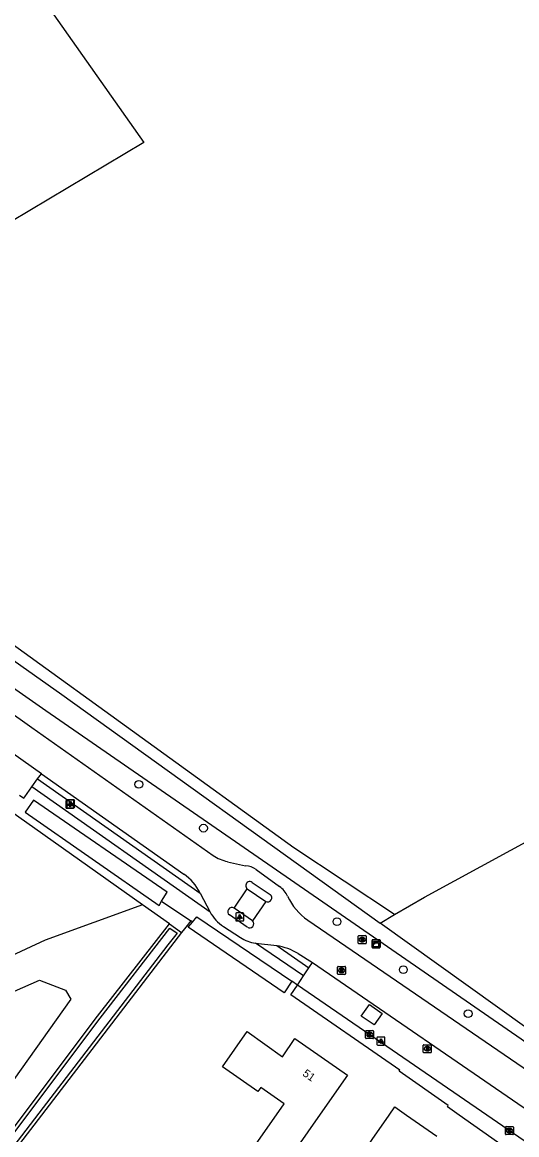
# Model space of a CAD drawing. Extents: x 163863 to 164644, y 379566 to 382155.
# Drawn here: x 164288.5 to 164350.3, y 381747.5 to 381886.6 of the extents above; entities that cross this region are included whole.
import ezdxf

# ---------------------------------------------------------------- set-up
doc = ezdxf.new("R2010")
doc.units = 0
for name, color, linetype in [('IMGEO_Boom', 7, 'Continuous'), ('IMGEO_Brandkraan', 7, 'Continuous'), ('IMGEO_Duiker', 7, 'Continuous'), ('IMGEO_Erf', 7, 'Continuous'), ('IMGEO_Fietspad_open', 7, 'Continuous'), ('IMGEO_Grasland_agrarisch', 7, 'Continuous'), ('IMGEO_Grasland_overig', 7, 'Continuous'), ('IMGEO_Groenvoorziening', 7, 'Continuous'), ('IMGEO_Kast', 7, 'Continuous'), ('IMGEO_Kolk', 7, 'Continuous'), ('IMGEO_Lichtpunt', 7, 'Continuous'), ('IMGEO_Loofbos', 7, 'Continuous'), ('IMGEO_Pand', 7, 'Continuous'), ('IMGEO_Pand_nummerreeks', 7, 'Continuous'), ('IMGEO_Parkeervlak_open', 7, 'Continuous'), ('IMGEO_Rijbaan_lokaal_gesloten', 7, 'Continuous'), ('IMGEO_Rijbaan_lokaal_open', 7, 'Continuous'), ('IMGEO_Rioolput', 7, 'Continuous'), ('IMGEO_Voetpad_onverhard', 7, 'Continuous'), ('IMGEO_Voetpad_open', 7, 'Continuous'), ('IMGEO_Waterloop', 7, 'Continuous')]:
    doc.layers.add(name, color=color, linetype=linetype)

msp = doc.modelspace()

# ---------------------------------------------------------------- linework, layer by layer
at = {"layer": 'IMGEO_Boom'}
for centre in [(164303.04, 381791.33), (164311.13, 381785.86), (164327.82, 381774.17), (164336.11, 381768.17), (164344.22, 381762.68)]:
    msp.add_circle(centre, 0.489, dxfattribs=at)
at = {"layer": 'IMGEO_Brandkraan'}
for p, q in [((164338.61, 381757.86), (164338.61, 381758.72)), ((164338.69, 381758.79), (164339.54, 381758.79)), ((164339.1, 381758.57), (164339.12, 381758.57)), ((164339.61, 381758.72), (164339.61, 381757.86)), ((164339.54, 381757.79), (164338.69, 381757.79)), ((164339.12, 381758.01), (164339.1, 381758.01))]:
    msp.add_line(p, q, dxfattribs=at)
for points in [[(164338.61, 381757.86), (164338.61, 381758.72)], [(164338.69, 381758.79), (164339.54, 381758.79)], [(164338.96, 381758.49), (164338.96, 381758.09), (164339.17, 381758.09)], [(164339.19, 381758.49), (164338.96, 381758.49)], [(164339.14, 381758.41), (164339.08, 381758.41), (164339.08, 381758.33)], [(164339.08, 381758.33), (164339.14, 381758.33)], [(164339.15, 381758.26), (164339.08, 381758.26), (164339.08, 381758.17)], [(164339.08, 381758.17), (164339.15, 381758.17)], [(164339.61, 381758.72), (164339.61, 381757.86)], [(164339.54, 381757.79), (164338.69, 381757.79)]]:
    msp.add_lwpolyline(points, dxfattribs=at)
for centre, radius, start, end in [((164338.69, 381758.71), 0.0765, 91.552, 178.448), ((164338.69, 381758.71), 0.0765, 91.552, 178.448), ((164339.14, 381758.37), 0.0379, 267.8285, 90.9355), ((164339.15, 381758.22), 0.0404, 269.8759, 90.5077), ((164339.18, 381758.34), 0.251, 268.6676, 293.5347), ((164339.19, 381758.34), 0.145, 59.4692, 91.5367), ((164339.22, 381758.39), 0.0922, 285.5137, 58.1501), ((164339.22, 381758.2), 0.105, 301.3115, 78.989), ((164339.54, 381758.71), 0.0765, 1.552, 88.448), ((164339.54, 381758.71), 0.0765, 1.552, 88.448), ((164338.69, 381757.86), 0.0765, 181.552, 268.448), ((164338.69, 381757.86), 0.0765, 181.552, 268.448), ((164339.54, 381757.86), 0.0765, 271.552, 358.448), ((164339.54, 381757.86), 0.0765, 271.552, 358.448)]:
    msp.add_arc(centre, radius, start, end, dxfattribs=at)
for centre, major_axis, ratio, start_param, end_param in [((164339.1, 381758.29), (-0.387, 0.002), 0.722429, 4.712389, 7.853982), ((164339.12, 381758.29), (-0.39, 0.002), 0.717154, 1.570796, 4.712389)]:
    msp.add_ellipse(centre, major_axis=major_axis, ratio=ratio, start_param=start_param, end_param=end_param, dxfattribs=at)
at = {"layer": 'IMGEO_Duiker'}
msp.add_lwpolyline([(164305.89, 381776.73), (164309.53, 381774.29)], dxfattribs=at)
at = {"layer": 'IMGEO_Erf'}
msp.add_lwpolyline([(164308.4, 381772.83), (164307.02, 381771.02), (164290.86, 381750), (164280.77, 381736.89), (164280.48, 381736.47), (164297.43, 381715.02)], dxfattribs=at)
at = {"layer": 'IMGEO_Fietspad_open'}
for points in [[(164289.68, 381791.02), (164290.39, 381792.01)], [(164290.39, 381792.01), (164310.71, 381777.75)], [(164311.95, 381775.37), (164289.68, 381791.02)], [(164323.62, 381767.41), (164317.65, 381771.48)], [(164320.29, 381771.18), (164324.32, 381768.39)], [(164323.62, 381767.41), (164324.32, 381768.39)]]:
    msp.add_lwpolyline(points, dxfattribs=at)
at = {"layer": 'IMGEO_Grasland_agrarisch'}
for points in [[(164278.81, 381906.76), (164279.85, 381905.36), (164303.69, 381871.55), (164284.62, 381860.24), (164259.76, 381889.45), (164267.39, 381895.77), (164258.03, 381908.47), (164254.79, 381905.94), (164252.4, 381909.27)], [(164335.01, 381775.05), (164338.75, 381777.23), (164392.73, 381806.6), (164404.25, 381812.22)]]:
    msp.add_lwpolyline(points, dxfattribs=at)
at = {"layer": 'IMGEO_Grasland_overig'}
for points in [[(164335.01, 381775.05), (164322.43, 381783.41), (164286.01, 381809.75), (164256.46, 381829.63), (164222.91, 381852.77), (164211.76, 381860.7), (164201.66, 381868.74), (164208.65, 381876.06), (164252.4, 381909.27)], [(164333.2, 381774), (164335.01, 381775.05)]]:
    msp.add_lwpolyline(points, dxfattribs=at)
at = {"layer": 'IMGEO_Groenvoorziening'}
for points in [[(164306.86, 381773.91), (164308.4, 381772.83)], [(164309.77, 381774.13), (164309.53, 381774.29), (164308.75, 381773.28), (164308.4, 381772.83)], [(164322.9, 381766.25), (164322.17, 381766.72)]]:
    msp.add_lwpolyline(points, dxfattribs=at)
at = {"layer": 'IMGEO_Kast'}
for p, q in [((164332.21, 381770.99), (164332.21, 381771.83)), ((164332.21, 381771.83), (164332.21, 381770.99)), ((164332.28, 381771.91), (164333.12, 381771.91)), ((164333.12, 381771.91), (164332.28, 381771.91)), ((164333.13, 381770.92), (164332.29, 381770.92)), ((164332.29, 381770.92), (164333.13, 381770.92)), ((164333.21, 381771.84), (164333.21, 381771)), ((164333.21, 381771), (164333.21, 381771.84))]:
    msp.add_line(p, q, dxfattribs=at)
for points in [[(164332.4, 381771.71), (164333, 381771.71), (164333, 381771.62), (164332.4, 381771.62), (164332.4, 381771.71)], [(164332.4, 381771.53), (164333, 381771.53), (164333, 381771.04), (164332.4, 381771.04), (164332.4, 381771.53)]]:
    msp.add_lwpolyline(points, dxfattribs=at)
msp.add_circle((164332.49, 381771.38), 0.0377, dxfattribs=at)
for centre, start, end in [((164332.29, 381771.84), 92.4484, 184.2845), ((164332.29, 381771.84), 92.4484, 184.2845), ((164332.29, 381770.99), 182.4484, 274.2845), ((164332.29, 381770.99), 182.4484, 274.2845), ((164333.13, 381771.84), 2.4484, 94.2845), ((164333.13, 381771.84), 2.4484, 94.2845), ((164333.13, 381770.99), 272.4484, 4.2845), ((164333.13, 381770.99), 272.4484, 4.2845)]:
    msp.add_arc(centre, 0.0779, start, end, dxfattribs=at)
at = {"layer": 'IMGEO_Kolk'}
for p, q in [((164331.4, 381759.64), (164331.4, 381760.49)), ((164331.47, 381760.57), (164332.32, 381760.57)), ((164332.32, 381759.57), (164331.47, 381759.57)), ((164331.91, 381759.79), (164331.88, 381759.79)), ((164331.89, 381760.35), (164331.91, 381760.35)), ((164332.4, 381760.49), (164332.4, 381759.64)), ((164348.89, 381747.63), (164348.89, 381748.48)), ((164348.96, 381748.56), (164349.81, 381748.56)), ((164349.37, 381748.34), (164349.4, 381748.34)), ((164349.89, 381748.48), (164349.89, 381747.63)), ((164349.81, 381747.56), (164348.96, 381747.56)), ((164349.4, 381747.78), (164349.37, 381747.78))]:
    msp.add_line(p, q, dxfattribs=at)
for points in [[(164331.4, 381759.64), (164331.4, 381760.49)], [(164331.47, 381760.57), (164332.32, 381760.57)], [(164332.32, 381759.57), (164331.47, 381759.57)], [(164331.72, 381760.27), (164331.84, 381760.27), (164331.84, 381760.12), (164331.97, 381760.27), (164332.14, 381760.27), (164331.99, 381760.12), (164332.14, 381759.87), (164331.99, 381759.87), (164331.91, 381760.03), (164331.84, 381759.97), (164331.84, 381759.87), (164331.72, 381759.87), (164331.72, 381760.27)], [(164332.4, 381760.49), (164332.4, 381759.64)], [(164348.89, 381747.63), (164348.89, 381748.48)], [(164348.96, 381748.56), (164349.81, 381748.56)], [(164349.89, 381748.48), (164349.89, 381747.63)], [(164349.81, 381747.56), (164348.96, 381747.56)], [(164349.21, 381748.26), (164349.33, 381748.26), (164349.33, 381748.11), (164349.46, 381748.26), (164349.62, 381748.26), (164349.48, 381748.11), (164349.63, 381747.86), (164349.48, 381747.86), (164349.39, 381748.02), (164349.33, 381747.96), (164349.33, 381747.86), (164349.21, 381747.86), (164349.21, 381748.26)]]:
    msp.add_lwpolyline(points, dxfattribs=at)
for centre, start, end in [((164331.47, 381760.49), 91.552, 178.448), ((164331.47, 381760.49), 91.552, 178.448), ((164331.47, 381759.64), 181.552, 268.448), ((164331.47, 381759.64), 181.552, 268.448), ((164332.32, 381760.49), 1.552, 88.448), ((164332.32, 381760.49), 1.552, 88.448), ((164332.32, 381759.64), 271.552, 358.448), ((164332.32, 381759.64), 271.552, 358.448), ((164348.96, 381748.48), 91.552, 178.448), ((164348.96, 381748.48), 91.552, 178.448), ((164349.81, 381748.48), 1.552, 88.448), ((164349.81, 381748.48), 1.552, 88.448), ((164348.96, 381747.63), 181.552, 268.448), ((164348.96, 381747.63), 181.552, 268.448), ((164349.81, 381747.63), 271.552, 358.448), ((164349.81, 381747.63), 271.552, 358.448)]:
    msp.add_arc(centre, 0.0765, start, end, dxfattribs=at)
for centre, major_axis, ratio, start_param, end_param in [((164331.88, 381760.07), (-0.387, 0.002), 0.722429, 4.712389, 7.853982), ((164331.91, 381760.07), (-0.39, 0.002), 0.717154, 1.570796, 4.712389), ((164349.37, 381748.06), (-0.387, 0.002), 0.722429, 4.712389, 7.853982), ((164349.4, 381748.06), (-0.39, 0.002), 0.717154, 1.570796, 4.712389)]:
    msp.add_ellipse(centre, major_axis=major_axis, ratio=ratio, start_param=start_param, end_param=end_param, dxfattribs=at)
at = {"layer": 'IMGEO_Lichtpunt'}
for p, q in [((164293.93, 381789.25), (164293.93, 381788.44)), ((164293.93, 381789.25), (164293.93, 381788.44)), ((164294.83, 381789.34), (164294.02, 381789.34)), ((164294.83, 381789.34), (164294.02, 381789.34)), ((164294.03, 381789.3), (164294.03, 381788.49)), ((164294.03, 381789.3), (164294.03, 381788.49)), ((164294.93, 381789.39), (164294.12, 381789.39)), ((164294.93, 381789.39), (164294.12, 381789.39)), ((164294.92, 381788.44), (164294.92, 381789.25)), ((164294.92, 381788.44), (164294.92, 381789.25)), ((164295.02, 381788.49), (164295.02, 381789.3)), ((164295.02, 381788.49), (164295.02, 381789.3)), ((164294.02, 381788.35), (164294.83, 381788.35)), ((164294.02, 381788.35), (164294.83, 381788.35)), ((164294.12, 381788.39), (164294.93, 381788.39)), ((164294.12, 381788.39), (164294.93, 381788.39)), ((164315.16, 381775.16), (164315.16, 381774.35)), ((164315.16, 381775.16), (164315.16, 381774.35)), ((164316.06, 381775.26), (164315.25, 381775.26)), ((164316.06, 381775.26), (164315.25, 381775.26)), ((164316.16, 381774.35), (164316.16, 381775.16)), ((164316.16, 381774.35), (164316.16, 381775.16)), ((164315.25, 381774.26), (164316.06, 381774.26)), ((164315.25, 381774.26), (164316.06, 381774.26)), ((164332.82, 381759.65), (164332.82, 381758.84)), ((164332.82, 381759.65), (164332.82, 381758.84)), ((164333.72, 381759.74), (164332.91, 381759.74)), ((164333.72, 381759.74), (164332.91, 381759.74)), ((164333.82, 381758.84), (164333.82, 381759.65)), ((164333.82, 381758.84), (164333.82, 381759.65)), ((164332.91, 381758.74), (164333.72, 381758.74)), ((164332.91, 381758.74), (164333.72, 381758.74))]:
    msp.add_line(p, q, dxfattribs=at)
for points in [[(164294.3, 381788.91), (164294.34, 381788.88), (164294.15, 381788.62), (164294.11, 381788.65), (164294.3, 381788.91)], [(164294.4, 381788.96), (164294.44, 381788.93), (164294.25, 381788.67), (164294.21, 381788.7), (164294.4, 381788.96)], [(164294.4, 381788.86), (164294.45, 381788.86), (164294.45, 381788.54), (164294.4, 381788.54), (164294.4, 381788.86)], [(164294.5, 381788.91), (164294.55, 381788.91), (164294.55, 381788.59), (164294.5, 381788.59), (164294.5, 381788.91)], [(164294.51, 381788.88), (164294.55, 381788.91), (164294.74, 381788.65), (164294.7, 381788.62), (164294.51, 381788.88)], [(164294.61, 381788.93), (164294.65, 381788.96), (164294.84, 381788.7), (164294.8, 381788.67), (164294.61, 381788.93)], [(164315.53, 381774.82), (164315.57, 381774.8), (164315.38, 381774.53), (164315.35, 381774.56), (164315.53, 381774.82)], [(164315.63, 381774.78), (164315.68, 381774.78), (164315.68, 381774.45), (164315.63, 381774.45), (164315.63, 381774.78)], [(164315.74, 381774.8), (164315.78, 381774.82), (164315.97, 381774.56), (164315.93, 381774.53), (164315.74, 381774.8)], [(164333.19, 381759.31), (164333.23, 381759.28), (164333.04, 381759.02), (164333.01, 381759.05), (164333.19, 381759.31)], [(164333.29, 381759.26), (164333.34, 381759.26), (164333.34, 381758.94), (164333.29, 381758.94), (164333.29, 381759.26)], [(164333.4, 381759.28), (164333.44, 381759.31), (164333.63, 381759.05), (164333.59, 381759.02), (164333.4, 381759.28)]]:
    msp.add_lwpolyline(points, dxfattribs=at)
for centre in [(164294.43, 381789.05), (164294.53, 381789.09), (164315.66, 381774.96), (164333.32, 381759.44)]:
    msp.add_circle(centre, 0.0994, dxfattribs=at)
for centre, start, end in [((164294.02, 381789.25), 90, 180), ((164294.02, 381789.25), 90, 180), ((164294.12, 381789.3), 90, 180), ((164294.12, 381789.3), 90, 180), ((164294.83, 381789.25), 0, 90), ((164294.83, 381789.25), 0, 90), ((164294.93, 381789.3), 0, 90), ((164294.93, 381789.3), 0, 90), ((164294.02, 381788.44), 180, 270), ((164294.02, 381788.44), 180, 270), ((164294.12, 381788.49), 180, 270), ((164294.12, 381788.49), 180, 270), ((164294.83, 381788.44), 270, 0), ((164294.83, 381788.44), 270, 360), ((164294.93, 381788.49), 270, 0), ((164294.93, 381788.49), 270, 360), ((164315.25, 381775.16), 90, 180), ((164315.25, 381775.16), 90, 180), ((164316.06, 381775.16), 0, 90), ((164316.06, 381775.16), 0, 90), ((164315.25, 381774.35), 180, 270), ((164315.25, 381774.35), 180, 270), ((164316.06, 381774.35), 270, 0), ((164316.06, 381774.35), 270, 360), ((164332.91, 381759.65), 90, 180), ((164332.91, 381759.65), 90, 180), ((164333.72, 381759.65), 0, 90), ((164333.72, 381759.65), 0, 90), ((164332.91, 381758.84), 180, 270), ((164332.91, 381758.84), 180, 270), ((164333.72, 381758.84), 270, 0), ((164333.72, 381758.84), 270, 360)]:
    msp.add_arc(centre, 0.0946, start, end, dxfattribs=at)
at = {"layer": 'IMGEO_Loofbos'}
msp.add_lwpolyline([(164303.49, 381776.26), (164286.77, 381788.13)], dxfattribs=at)
at = {"layer": 'IMGEO_Pand'}
for points in [[(164320.98, 381743.29), (164317.32, 381745.85), (164321.21, 381751.42), (164318.29, 381753.45), (164317.93, 381752.94), (164313.51, 381756.03), (164316.59, 381760.45), (164320.99, 381757.29), (164322.57, 381759.56), (164329.13, 381754.99), (164325.14, 381749.26), (164322.27, 381745.14), (164320.98, 381743.29)], [(164327.45, 381732.26), (164325.29, 381734.32), (164328.83, 381740.07), (164329.72, 381741.52), (164331.14, 381740.65), (164332.5, 381742.77), (164330.37, 381744.25), (164332.23, 381746.93), (164334.36, 381750), (164335.05, 381751.01), (164336.5, 381750), (164340.32, 381747.35)]]:
    msp.add_lwpolyline(points, dxfattribs=at)
at = {"layer": 'IMGEO_Parkeervlak_open'}
for points in [[(164290.39, 381792.01), (164290.86, 381792.66)], [(164288.11, 381790), (164288.68, 381789.6), (164288.79, 381789.76), (164289.68, 381791.02)], [(164324.32, 381768.39), (164324.77, 381769.07)], [(164322.9, 381766.25), (164323.62, 381767.41)], [(164332.46, 381761.27), (164330.86, 381762.38), (164331.88, 381763.83), (164333.47, 381762.71), (164332.46, 381761.27)]]:
    msp.add_lwpolyline(points, dxfattribs=at)
at = {"layer": 'IMGEO_Rijbaan_lokaal_gesloten'}
for points in [[(164242.76, 381832.06), (164272.36, 381810.74), (164289.67, 381798.44), (164312.34, 381782.45)], [(164290.86, 381792.66), (164287.31, 381795.18), (164274.05, 381804.4), (164268.51, 381808.32), (164257.97, 381815.61)], [(164290.86, 381792.66), (164308.66, 381780.12)], [(164314.13, 381781.67), (164316.4, 381781.16)], [(164317.71, 381780.68), (164320.63, 381778.58)], [(164317.21, 381779.08), (164319.45, 381777.57)], [(164310.71, 381777.75), (164311.95, 381775.37)], [(164316.61, 381773.48), (164314.37, 381775.01)], [(164313.62, 381773.55), (164315.74, 381772.18)], [(164324.17, 381774.36), (164359.82, 381750), (164360.25, 381749.71)], [(164317.65, 381771.48), (164320.29, 381771.18)], [(164322.96, 381770.2), (164324.77, 381769.07)], [(164324.77, 381769.07), (164352.54, 381750), (164383.72, 381728.59), (164408.35, 381711.66)]]:
    msp.add_lwpolyline(points, dxfattribs=at)
for centre, radius, start, end in [((164315.3, 381786.79), 5.25, 235.7526, 257.1801), ((164316.4, 381779.12), 2.03, 49.8858, 90.0498), ((164305.19, 381775.04), 6.15, 26.1718, 55.5997), ((164316.91, 381778.68), 0.501, 52.9472, 232.9472), ((164319.15, 381777.15), 0.514, 242.8512, 54.051), ((164318.55, 381775.83), 3.45, 26.2052, 52.8803), ((164328.18, 381780.32), 7.17, 204.3923, 236.0546), ((164317.09, 381778.42), 5.98, 210.6273, 234.4876), ((164314.67, 381775.42), 0.512, 56.8407, 233.9176), ((164316.9, 381773.9), 0.507, 235.4158, 45.6702), ((164318.52, 381776.86), 5.45, 239.2862, 260.7957), ((164319, 381763.57), 7.71, 59.1787, 80.3756)]:
    msp.add_arc(centre, radius, start, end, dxfattribs=at)
at = {"layer": 'IMGEO_Rijbaan_lokaal_open'}
for points in [[(164314.95, 381775.85), (164316.6, 381778.28)], [(164316.6, 381778.28), (164318.92, 381776.69)], [(164318.92, 381776.69), (164317.25, 381774.26)], [(164317.25, 381774.26), (164314.95, 381775.85)]]:
    msp.add_lwpolyline(points, dxfattribs=at)
at = {"layer": 'IMGEO_Rioolput'}
for p, q in [((164330.47, 381771.5), (164330.47, 381772.35)), ((164330.55, 381772.43), (164331.4, 381772.43)), ((164330.96, 381772.2), (164330.99, 381772.2)), ((164331.47, 381772.35), (164331.47, 381771.5)), ((164331.4, 381771.42), (164330.55, 381771.42)), ((164330.98, 381771.65), (164330.96, 381771.65)), ((164327.89, 381767.65), (164327.89, 381768.5)), ((164327.97, 381768.58), (164328.82, 381768.58)), ((164328.38, 381768.36), (164328.41, 381768.36)), ((164328.4, 381767.8), (164328.38, 381767.8)), ((164328.89, 381768.5), (164328.89, 381767.65)), ((164328.82, 381767.58), (164327.97, 381767.58))]:
    msp.add_line(p, q, dxfattribs=at)
for points in [[(164330.47, 381771.5), (164330.47, 381772.35)], [(164330.55, 381772.43), (164331.4, 381772.43)], [(164331.06, 381772.12), (164330.81, 381772.12), (164330.81, 381771.72)], [(164330.99, 381772.04), (164330.93, 381772.04), (164330.93, 381771.96)], [(164330.93, 381771.96), (164330.98, 381771.96)], [(164331.47, 381772.35), (164331.47, 381771.5)], [(164331.4, 381771.42), (164330.55, 381771.42)], [(164330.81, 381771.72), (164330.93, 381771.72), (164330.93, 381771.89), (164330.94, 381771.89)], [(164330.99, 381771.86), (164331.06, 381771.72), (164331.2, 381771.72), (164331.14, 381771.85)], [(164327.89, 381767.65), (164327.89, 381768.5)], [(164327.97, 381768.58), (164328.82, 381768.58)], [(164328.48, 381768.27), (164328.23, 381768.28), (164328.23, 381767.88)], [(164328.23, 381767.88), (164328.35, 381767.88), (164328.35, 381768.04), (164328.37, 381768.04)], [(164328.41, 381768.2), (164328.35, 381768.2), (164328.35, 381768.11)], [(164328.35, 381768.11), (164328.41, 381768.11)], [(164328.41, 381768.01), (164328.48, 381767.88), (164328.62, 381767.88), (164328.56, 381768)], [(164328.89, 381768.5), (164328.89, 381767.65)], [(164328.82, 381767.58), (164327.97, 381767.58)]]:
    msp.add_lwpolyline(points, dxfattribs=at)
for centre, radius, start, end in [((164330.55, 381772.35), 0.0765, 91.552, 178.448), ((164330.55, 381772.35), 0.0765, 91.552, 178.448), ((164330.97, 381772.15), 0.19, 274.7715, 282.9687), ((164330.99, 381771.95), 0.0964, 77.0061, 93.1865), ((164331.01, 381772), 0.0378, 276.6634, 79.6772), ((164331.06, 381772.01), 0.109, 350.3612, 89.416), ((164331.06, 381772.01), 0.112, 277.5842, 350.9817), ((164331.4, 381772.35), 0.0765, 1.552, 88.448), ((164331.4, 381772.35), 0.0765, 1.552, 88.448), ((164330.55, 381771.5), 0.0765, 181.552, 268.448), ((164330.55, 381771.5), 0.0765, 181.552, 268.448), ((164330.94, 381771.83), 0.0533, 26.0293, 88.6989), ((164331.04, 381771.8), 0.108, 29.5134, 73.7905), ((164331.4, 381771.5), 0.0765, 271.552, 358.448), ((164331.4, 381771.5), 0.0765, 271.552, 358.448), ((164327.97, 381768.5), 0.0765, 91.552, 178.448), ((164327.97, 381768.5), 0.0765, 91.552, 178.448), ((164328.36, 381767.99), 0.0533, 26.0293, 88.6989), ((164328.41, 381768.1), 0.0964, 77.0061, 93.1865), ((164328.39, 381768.3), 0.19, 274.7715, 282.9687), ((164328.43, 381768.16), 0.0378, 276.6634, 79.6772), ((164328.48, 381768.17), 0.109, 350.3612, 89.416), ((164328.48, 381768.16), 0.112, 277.5842, 350.9817), ((164328.46, 381767.95), 0.108, 29.5134, 73.7905), ((164328.82, 381768.5), 0.0765, 1.552, 88.448), ((164328.82, 381768.5), 0.0765, 1.552, 88.448), ((164327.97, 381767.65), 0.0765, 181.552, 268.448), ((164327.97, 381767.65), 0.0765, 181.552, 268.448), ((164328.82, 381767.65), 0.0765, 271.552, 358.448), ((164328.82, 381767.65), 0.0765, 271.552, 358.448)]:
    msp.add_arc(centre, radius, start, end, dxfattribs=at)
for centre, major_axis, ratio, start_param, end_param in [((164330.96, 381771.92), (-0.387, 0.002), 0.722429, 4.712389, 7.853982), ((164330.98, 381771.92), (-0.39, 0.002), 0.717154, 1.570796, 4.712389), ((164328.38, 381768.08), (-0.387, 0.002), 0.722429, 4.712389, 7.853982), ((164328.4, 381768.08), (-0.39, 0.002), 0.717154, 1.570796, 4.712389)]:
    msp.add_ellipse(centre, major_axis=major_axis, ratio=ratio, start_param=start_param, end_param=end_param, dxfattribs=at)
at = {"layer": 'IMGEO_Voetpad_onverhard'}
for points in [[(164303.49, 381776.26), (164291.35, 381771.86), (164264.62, 381759.45), (164263.5, 381758.93), (164262.44, 381758.43), (164241.55, 381750), (164220.61, 381740.51), (164216.3, 381738.03), (164214.93, 381737.24), (164212.4, 381737.16), (164209.89, 381736.86), (164207.42, 381736.34), (164205.01, 381735.6), (164202.67, 381734.64), (164200.43, 381733.48), (164199.53, 381732.94), (164085.49, 381652.45), (164019.17, 381605.94), (164016.82, 381609.1)], [(164306.86, 381773.91), (164303.49, 381776.26)], [(164248.01, 381711.61), (164278.67, 381737.67), (164282.91, 381742.46), (164288.58, 381750), (164297.87, 381762.34), (164306.86, 381773.91)], [(164244.52, 381712.92), (164222.03, 381737.72), (164227.2, 381740.33), (164252.2, 381750), (164290.62, 381766.86), (164293.86, 381765.63), (164294.55, 381764.48), (164280.26, 381744.42), (164244.52, 381712.92)]]:
    msp.add_lwpolyline(points, dxfattribs=at)
at = {"layer": 'IMGEO_Voetpad_open'}
for points in [[(164309.77, 381774.13), (164310.29, 381774.76), (164322.17, 381766.72)], [(164322.17, 381766.72), (164321.2, 381765.27), (164309.22, 381773.47), (164309.77, 381774.13)], [(164366.58, 381736.25), (164365.24, 381734.41), (164343.09, 381750), (164341.65, 381751.02), (164341.73, 381751.2), (164335.58, 381755.47), (164335.67, 381755.63), (164322.06, 381765.02), (164322.9, 381766.25)], [(164366.58, 381736.25), (164346.56, 381750), (164322.9, 381766.25)]]:
    msp.add_lwpolyline(points, dxfattribs=at)
at = {"layer": 'IMGEO_Waterloop'}
for points in [[(164362.02, 381753.2), (164361.43, 381751.86), (164361.27, 381751.98), (164350.84, 381759.48), (164291.42, 381800.51), (164261.83, 381821.18), (164221.97, 381849.02), (164223.06, 381850.62)], [(164223.06, 381850.62), (164244.45, 381836.35), (164263.51, 381823.64), (164264.6, 381822.91), (164293.41, 381802.56), (164333.2, 381774)], [(164306.57, 381777.85), (164289.86, 381789.35), (164288.82, 381787.87), (164305.57, 381776.21), (164305.89, 381776.73), (164306.57, 381777.85)], [(164280.13, 381736.69), (164280.15, 381736.16), (164297.15, 381715.02), (164296.61, 381714.6), (164296.14, 381715.2), (164283.99, 381730.76), (164279.31, 381736.01), (164279.02, 381736.19), (164248.92, 381711.15), (164248.75, 381711.35), (164248.58, 381711.56), (164278.96, 381737.38), (164283.23, 381742.2), (164288.91, 381749.75), (164298.2, 381762.09), (164306.94, 381773.35), (164307.82, 381772.74), (164306.69, 381771.27), (164290.54, 381750.25), (164280.45, 381737.13), (164280.13, 381736.69)], [(164362.02, 381753.2), (164361.55, 381753.54), (164351.55, 381760.84), (164333.2, 381774)]]:
    msp.add_lwpolyline(points, dxfattribs=at)

# ---------------------------------------------------------------- texts
at = {"layer": 'IMGEO_Pand_nummerreeks'}
msp.add_text('51', height=1, rotation=325.1344, dxfattribs=at).set_placement((164323.44, 381754.99))

doc.saveas('drawing.dxf')
